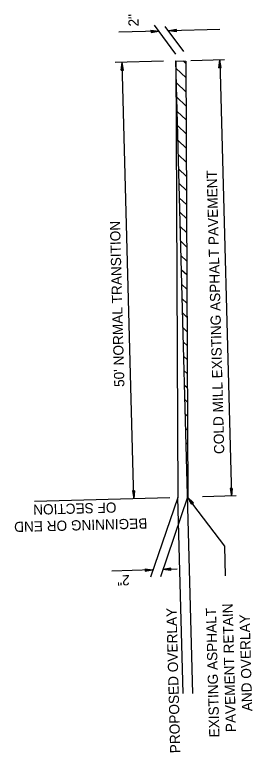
# Model space of a CAD drawing. Extents: x 1926836 to 1933254, y 596317 to 604524.
# Drawn here: x 1931688.6 to 1931828.5, y 604089.8 to 604524 of the extents above; entities that cross this region are included whole.
import ezdxf

# ---------------------------------------------------------------- set-up
doc = ezdxf.new("R2010")
doc.units = 0
doc.layers.add('Default', color=7, linetype='Continuous')
doc.layers.add('R_Annotation', color=7, linetype='Continuous')

msp = doc.modelspace()

# ---------------------------------------------------------------- linework, layer by layer
at = {"layer": 'Default'}
for p, q in [((1931773.52, 604514.4), (1931749.99, 604513.77)), ((1931768.84, 604514.94), (1931773.52, 604514.4)), ((1931768.84, 604514.94), (1931772.62, 604514.38)), ((1931768.84, 604514.94), (1931768.87, 604513.62)), ((1931768.84, 604514.73), (1931771.96, 604514.36)), ((1931768.84, 604514.73), (1931771.07, 604514.33)), ((1931768.85, 604514.5), (1931770.4, 604514.32)), ((1931768.85, 604514.5), (1931769.52, 604514.29)), ((1931768.86, 604514.05), (1931771.07, 604514.33)), ((1931768.86, 604514.05), (1931770.4, 604514.32)), ((1931768.86, 604514.27), (1931769.52, 604514.29)), ((1931768.87, 604513.62), (1931773.52, 604514.4)), ((1931768.87, 604513.84), (1931772.62, 604514.38)), ((1931768.87, 604513.84), (1931771.96, 604514.36)), ((1931783.42, 604500.9), (1931770.97, 604517.89)), ((1931788.27, 604502.36), (1931777.22, 604517.17)), ((1931809.48, 604515.37), (1931779.28, 604514.55)), ((1931783.93, 604515.35), (1931779.28, 604514.55)), ((1931783.96, 604514.02), (1931779.28, 604514.55)), ((1931783.93, 604515.35), (1931779.95, 604514.57)), ((1931783.96, 604514.25), (1931779.95, 604514.57)), ((1931783.93, 604515.13), (1931780.84, 604514.6)), ((1931783.96, 604514.25), (1931780.84, 604514.6)), ((1931783.93, 604515.13), (1931781.51, 604514.61)), ((1931783.95, 604514.45), (1931781.51, 604514.61)), ((1931783.94, 604514.9), (1931782.4, 604514.64)), ((1931783.95, 604514.45), (1931782.4, 604514.64)), ((1931783.94, 604514.9), (1931783.05, 604514.66)), ((1931783.95, 604514.68), (1931783.05, 604514.66)), ((1931783.96, 604514.02), (1931783.93, 604515.35)), ((1931776.21, 604496.65), (1931747.8, 604495.89)), ((1931783.53, 604496.85), (1931784.66, 604239.77)), ((1931793.53, 604124.49), (1931783.53, 604496.85)), ((1931783.53, 604496.85), (1931789.32, 604496.77)), ((1931789.32, 604496.77), (1931790.45, 604239.7)), ((1931812.19, 604497.39), (1931792.21, 604496.85)), ((1931808.76, 604492.85), (1931809.29, 604497.31)), ((1931808.76, 604492.85), (1931809.31, 604496.63)), ((1931809.29, 604497.31), (1931816.18, 604240.62)), ((1931810.08, 604492.89), (1931809.29, 604497.31)), ((1931809.86, 604492.88), (1931809.31, 604496.63)), ((1931751.25, 604491.31), (1931751.78, 604496)), ((1931751.46, 604491.31), (1931751.81, 604495.09)), ((1931751.46, 604491.31), (1931751.83, 604494.44)), ((1931751.69, 604491.32), (1931751.85, 604493.56)), ((1931751.69, 604491.32), (1931751.87, 604492.88)), ((1931758.68, 604239.07), (1931751.78, 604496)), ((1931752.57, 604491.34), (1931751.78, 604496)), ((1931752.57, 604491.34), (1931751.81, 604495.09)), ((1931752.35, 604491.34), (1931751.83, 604494.44)), ((1931752.35, 604491.34), (1931751.85, 604493.56)), ((1931752.13, 604491.33), (1931751.87, 604492.88)), ((1931808.76, 604492.85), (1931810.08, 604492.89)), ((1931808.96, 604492.85), (1931809.33, 604495.75)), ((1931808.96, 604492.85), (1931809.35, 604495.1)), ((1931809.2, 604492.86), (1931809.37, 604494.21)), ((1931809.2, 604492.86), (1931809.39, 604493.54)), ((1931809.86, 604492.88), (1931809.33, 604495.75)), ((1931809.64, 604492.87), (1931809.35, 604495.1)), ((1931809.64, 604492.87), (1931809.37, 604494.21)), ((1931809.41, 604492.87), (1931809.39, 604493.54)), ((1931751.25, 604491.31), (1931752.57, 604491.34)), ((1931752.13, 604491.33), (1931751.89, 604492)), ((1931751.91, 604491.32), (1931751.89, 604492)), ((1931816.73, 604245.1), (1931815.41, 604245.06)), ((1931816.73, 604245.1), (1931815.41, 604245.06)), ((1931815.41, 604245.06), (1931816.18, 604240.62)), ((1931815.41, 604245.06), (1931816.16, 604241.3)), ((1931815.41, 604245.06), (1931816.18, 604240.62)), ((1931815.41, 604245.06), (1931816.16, 604241.3)), ((1931815.61, 604245.07), (1931816.14, 604242.18)), ((1931815.61, 604245.07), (1931816.12, 604242.85)), ((1931815.61, 604245.07), (1931816.14, 604242.18)), ((1931815.61, 604245.07), (1931816.12, 604242.85)), ((1931815.85, 604245.07), (1931816.1, 604243.74)), ((1931815.85, 604245.07), (1931816.08, 604244.41)), ((1931815.85, 604245.07), (1931816.1, 604243.74)), ((1931815.85, 604245.07), (1931816.08, 604244.41)), ((1931816.06, 604245.08), (1931816.08, 604244.41)), ((1931816.06, 604245.08), (1931816.08, 604244.41)), ((1931816.29, 604245.09), (1931816.1, 604243.74)), ((1931816.29, 604245.09), (1931816.1, 604243.74)), ((1931816.29, 604245.09), (1931816.12, 604242.85)), ((1931816.29, 604245.09), (1931816.12, 604242.85)), ((1931816.51, 604245.09), (1931816.14, 604242.18)), ((1931816.51, 604245.09), (1931816.14, 604242.18)), ((1931816.51, 604245.09), (1931816.16, 604241.3)), ((1931816.51, 604245.09), (1931816.16, 604241.3)), ((1931816.73, 604245.1), (1931816.18, 604240.62)), ((1931816.73, 604245.1), (1931816.18, 604240.62)), ((1931759.22, 604243.76), (1931757.89, 604243.72)), ((1931757.89, 604243.72), (1931758.68, 604239.07)), ((1931758.11, 604243.73), (1931758.64, 604240.64)), ((1931758.11, 604243.73), (1931758.66, 604239.75)), ((1931758.34, 604243.74), (1931758.6, 604242.19)), ((1931758.34, 604243.74), (1931758.62, 604241.53)), ((1931758.56, 604243.74), (1931758.57, 604243.08)), ((1931758.77, 604243.75), (1931758.57, 604243.08)), ((1931758.77, 604243.75), (1931758.6, 604242.19)), ((1931759, 604243.75), (1931758.62, 604241.53)), ((1931759, 604243.75), (1931758.64, 604240.64)), ((1931759.22, 604243.76), (1931758.66, 604239.75)), ((1931759.22, 604243.76), (1931758.68, 604239.07)), ((1931819.08, 604240.7), (1931799.1, 604240.16)), ((1931780.01, 604239.65), (1931700.17, 604237.51)), ((1931784.66, 604239.77), (1931768.58, 604192.91)), ((1931790.43, 604239.93), (1931774.36, 604193.07)), ((1931787.77, 604124.34), (1931784.67, 604239.77)), ((1931812.3, 604211.2), (1931790.43, 604239.93)), ((1931792.77, 604235.78), (1931790.43, 604239.93)), ((1931793.85, 604236.69), (1931790.43, 604239.93)), ((1931792.77, 604236), (1931790.89, 604239.28)), ((1931793.63, 604236.68), (1931790.89, 604239.28)), ((1931793.64, 604236.46), (1931791.36, 604238.63)), ((1931792.77, 604236), (1931791.36, 604238.63)), ((1931792.98, 604236.01), (1931791.82, 604237.96)), ((1931793.41, 604236.46), (1931791.82, 604237.96)), ((1931793.41, 604236.46), (1931792.27, 604237.54)), ((1931792.98, 604236.01), (1931792.27, 604237.54)), ((1931793.19, 604236.24), (1931792.74, 604236.88)), ((1931793.19, 604236.24), (1931792.74, 604236.88)), ((1931792.77, 604235.78), (1931793.85, 604236.69)), ((1931812.77, 604193.66), (1931812.3, 604211.2)), ((1931769.8, 604197.17), (1931745.82, 604196.52)), ((1931765.34, 604197.71), (1931769.8, 604197.17)), ((1931765.34, 604197.71), (1931765.37, 604196.38)), ((1931765.34, 604197.49), (1931768.24, 604197.12)), ((1931765.34, 604197.49), (1931769.14, 604197.15)), ((1931765.35, 604197.26), (1931766.7, 604197.08)), ((1931765.35, 604197.26), (1931767.59, 604197.11)), ((1931765.36, 604196.82), (1931766.7, 604197.08)), ((1931765.36, 604196.82), (1931766.04, 604197.06)), ((1931765.36, 604197.05), (1931766.04, 604197.06)), ((1931765.37, 604196.38), (1931769.8, 604197.17)), ((1931765.37, 604196.38), (1931769.14, 604197.15)), ((1931765.37, 604196.61), (1931768.24, 604197.12)), ((1931765.37, 604196.61), (1931767.59, 604197.11)), ((1931780.45, 604198.12), (1931775.8, 604197.33)), ((1931784.23, 604197.55), (1931775.8, 604197.33)), ((1931780.49, 604196.78), (1931775.8, 604197.33)), ((1931780.46, 604197.9), (1931776.47, 604197.34)), ((1931780.49, 604196.78), (1931776.47, 604197.34)), ((1931780.46, 604197.9), (1931777.35, 604197.37)), ((1931780.48, 604197.01), (1931777.35, 604197.37)), ((1931780.46, 604197.67), (1931778.01, 604197.39)), ((1931780.48, 604197.01), (1931778.01, 604197.39)), ((1931780.46, 604197.67), (1931778.91, 604197.41)), ((1931780.47, 604197.23), (1931778.91, 604197.41)), ((1931780.47, 604197.45), (1931779.8, 604197.43)), ((1931780.47, 604197.23), (1931779.8, 604197.43)), ((1931780.49, 604196.78), (1931780.45, 604198.12))]:
    msp.add_line(p, q, dxfattribs=at)
at = {"layer": 'R_Annotation'}
for p, q in [((1931789.33, 604495.33), (1931787.79, 604496.79)), ((1931789.36, 604487.03), (1931783.65, 604492.45)), ((1931789.4, 604478.73), (1931783.88, 604483.97)), ((1931789.44, 604470.43), (1931784.1, 604475.48)), ((1931789.47, 604462.13), (1931784.33, 604467)), ((1931789.51, 604453.83), (1931784.56, 604458.52)), ((1931789.55, 604445.53), (1931784.79, 604450.04)), ((1931789.58, 604437.23), (1931785.02, 604441.55)), ((1931789.62, 604428.92), (1931785.25, 604433.07)), ((1931789.66, 604420.62), (1931785.48, 604424.58)), ((1931789.69, 604412.32), (1931785.71, 604416.1)), ((1931789.73, 604404.02), (1931785.93, 604407.62)), ((1931789.77, 604395.72), (1931786.16, 604399.14)), ((1931789.8, 604387.42), (1931786.39, 604390.65)), ((1931789.84, 604379.12), (1931786.62, 604382.17)), ((1931789.88, 604370.82), (1931786.84, 604373.69)), ((1931789.91, 604362.52), (1931787.07, 604365.21)), ((1931789.95, 604354.21), (1931787.3, 604356.73)), ((1931789.99, 604345.91), (1931787.53, 604348.24)), ((1931790.02, 604337.61), (1931787.75, 604339.76)), ((1931790.06, 604329.31), (1931787.98, 604331.28)), ((1931790.09, 604321.01), (1931788.21, 604322.8)), ((1931790.13, 604312.71), (1931788.44, 604314.31)), ((1931790.17, 604304.41), (1931788.67, 604305.83)), ((1931790.2, 604296.11), (1931788.89, 604297.35)), ((1931790.24, 604287.81), (1931789.12, 604288.87)), ((1931790.28, 604279.5), (1931789.35, 604280.39)), ((1931790.31, 604271.2), (1931789.58, 604271.9)), ((1931790.35, 604262.9), (1931789.8, 604263.42)), ((1931790.39, 604254.6), (1931790.03, 604254.94)), ((1931790.42, 604246.3), (1931790.26, 604246.46))]:
    msp.add_line(p, q, dxfattribs=at)

# ---------------------------------------------------------------- texts
at = {"layer": 'Default'}
for s, rotation, p in [('2"', 91.5377, (1931761.61, 604517.21)), ('COLD MILL EXISTING ASPHALT PAVEMENT', 91.5377, (1931812.05, 604265.46)), ("50' NORMAL TRANSITION", 91.5377, (1931753.22, 604304.96)), ('OF SECTION', 181.5377, (1931748.4, 604236.93)), ('BEGINNING OR END', 181.5377, (1931766.6, 604227.55)), ('2"', 181.5377, (1931756.22, 604194.14)), ('PAVEMENT RETAIN', 91.5377, (1931818.94, 604101.73)), ('PROPOSED OVERLAY', 91.5377, (1931786.14, 604089.32)), ('EXISTING ASPHALT', 91.5377, (1931809.16, 604098.63)), ('AND OVERLAY', 91.5377, (1931828.48, 604114.03))]:
    msp.add_text(s, height=6, rotation=rotation, dxfattribs=at).set_placement(p)

doc.saveas('drawing.dxf')
